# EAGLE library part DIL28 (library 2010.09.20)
Dual In Line
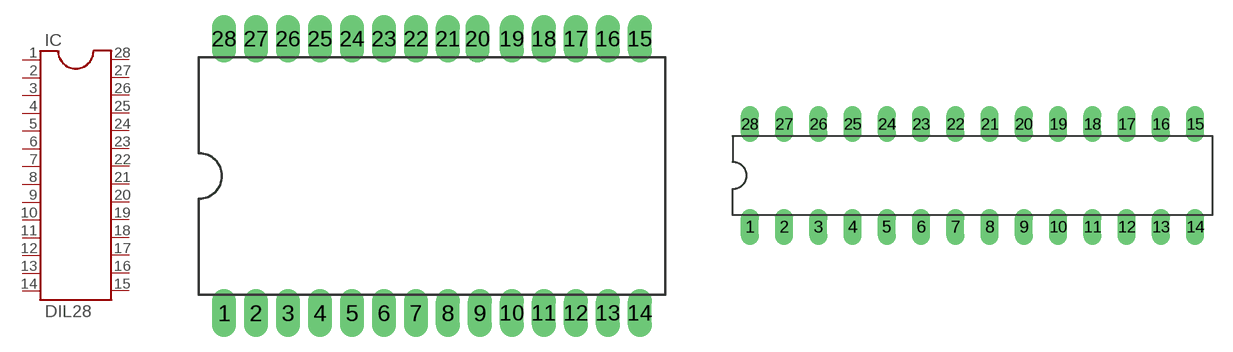
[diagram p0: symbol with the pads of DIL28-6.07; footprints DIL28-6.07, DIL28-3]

Designator prefix IC

## DIL28-6.07  [DIL28-6.07]
1  1  pas
2  2  pas
3  3  pas
4  4  pas
5  5  pas
6  6  pas
7  7  pas
8  8  pas
9  9  pas
10  10  pas
11  11  pas
12  12  pas
13  13  pas
14  14  pas
15  15  pas
16  16  pas
17  17  pas
18  18  pas
19  19  pas
20  20  pas
21  21  pas
22  22  pas
23  23  pas
24  24  pas
25  25  pas
26  26  pas
27  27  pas
28  28  pas

## DIL28-3  [DIL28-3]
Pads as for DIL28-6.07

## DIL28-4  [DIL28-4]
Pads as for DIL28-6.07

## DIL28  [DIL28-6]
Pads as for DIL28-6.07

## Footprint DIL28-6.07 (pad centres in mm)
Dual In Line Package 0.6 inch 0.07 pitch Drawn by D Lue Choy &micro; 2010.09.20
drill 0.813 long: 1 -11.557,-7.62; 2 -9.779,-7.62; 3 -8.001,-7.62; 4 -6.223,-7.62; 5 -4.445,-7.62; 6 -2.667,-7.62; 7 -0.889,-7.62; 8 0.889,-7.62; 9 2.667,-7.62; 10 4.445,-7.62; 11 6.223,-7.62; 12 8.001,-7.62; 13 9.779,-7.62; 14 11.557,-7.62; 15 11.557,7.62; 16 9.779,7.62; 17 8.001,7.62; 18 6.223,7.62; 19 4.445,7.62; 20 2.54,7.62; 21 0.889,7.62; 22 -0.889,7.62; 23 -2.667,7.62; 24 -4.445,7.62; 25 -6.223,7.62; 26 -8.001,7.62; 27 -9.779,7.62; 28 -11.557,7.62

## Footprint DIL28-3 (pad centres in mm)
Dual In Line Package Small
drill 0.813 long: 1 -16.51,-3.81; 2 -13.97,-3.81; 3 -11.43,-3.81; 4 -8.89,-3.81; 5 -6.35,-3.81; 6 -3.81,-3.81; 7 -1.27,-3.81; 8 1.27,-3.81; 9 3.81,-3.81; 10 6.35,-3.81; 11 8.89,-3.81; 12 11.43,-3.81; 13 13.97,-3.81; 14 16.51,-3.81; 15 16.51,3.81; 16 13.97,3.81; 17 11.43,3.81; 18 8.89,3.81; 19 6.35,3.81; 20 3.81,3.81; 21 1.27,3.81; 22 -1.27,3.81; 23 -3.81,3.81; 24 -6.35,3.81; 25 -8.89,3.81; 26 -11.43,3.81; 27 -13.97,3.81; 28 -16.51,3.81

## Footprint DIL28-4 (pad centres in mm)
Dual In Line Package
drill 0.813 long: 1 -16.51,-5.08; 2 -13.97,-5.08; 3 -11.43,-5.08; 4 -8.89,-5.08; 5 -6.35,-5.08; 6 -3.81,-5.08; 7 -1.27,-5.08; 8 1.27,-5.08; 9 3.81,-5.08; 10 6.35,-5.08; 11 8.89,-5.08; 12 11.43,-5.08; 13 13.97,-5.08; 14 16.51,-5.08; 15 16.51,5.08; 16 13.97,5.08; 17 11.43,5.08; 18 8.89,5.08; 19 6.35,5.08; 20 3.81,5.08; 21 1.27,5.08; 22 -1.27,5.08; 23 -3.81,5.08; 24 -6.35,5.08; 25 -8.89,5.08; 26 -11.43,5.08; 27 -13.97,5.08; 28 -16.51,5.08

## Footprint DIL28-6 (pad centres in mm)
Dual In Line Package 0.6 inch
drill 0.813 long: 1 -16.51,-7.62; 2 -13.97,-7.62; 3 -11.43,-7.62; 4 -8.89,-7.62; 5 -6.35,-7.62; 6 -3.81,-7.62; 7 -1.27,-7.62; 8 1.27,-7.62; 9 3.81,-7.62; 10 6.35,-7.62; 11 8.89,-7.62; 12 11.43,-7.62; 13 13.97,-7.62; 14 16.51,-7.62; 15 16.51,7.62; 16 13.97,7.62; 17 11.43,7.62; 18 8.89,7.62; 19 6.35,7.62; 20 3.81,7.62; 21 1.27,7.62; 22 -1.27,7.62; 23 -3.81,7.62; 24 -6.35,7.62; 25 -8.89,7.62; 26 -11.43,7.62; 27 -13.97,7.62; 28 -16.51,7.62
